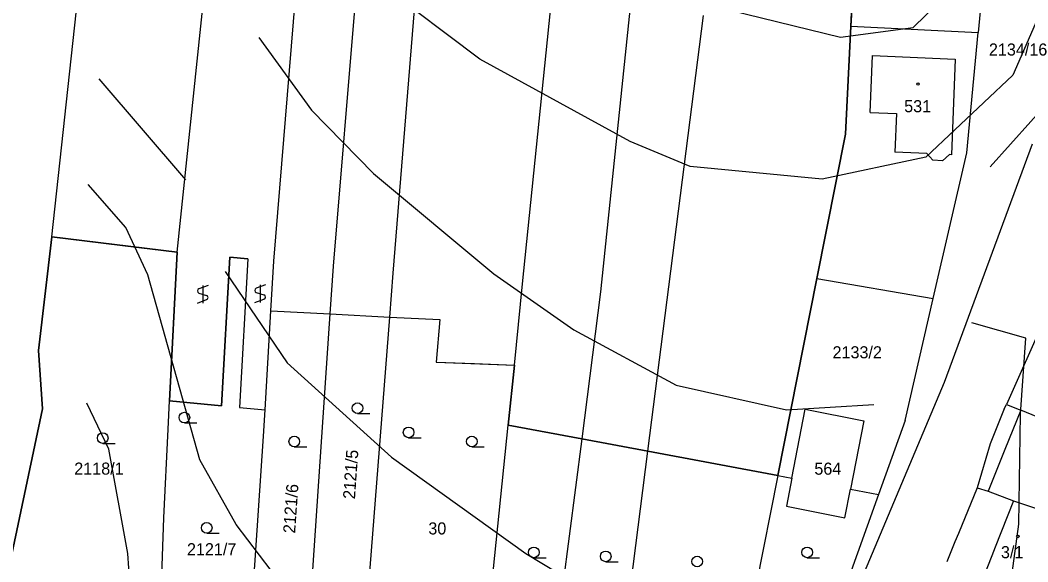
# Model space of a CAD drawing. Extents: x -555860 to -552701, y -1187050 to -1182291.
# Drawn here: x -554286.6 to -554144.7, y -1184272.3 to -1184196.1 of the extents above; entities that cross this region are included whole.
import ezdxf

# ---------------------------------------------------------------- set-up
doc = ezdxf.new("R2010")
doc.units = 0
for name, color, linetype in [('CYKLISTI_stav', 7, 'Continuous'), ('LEG_2b', 7, 'Continuous'), ('Level 25', 7, 'Continuous'), ('Level 32', 7, 'Continuous'), ('Level 40', 7, 'Continuous'), ('Level 41', 7, 'Continuous'), ('navrh_BV', 7, 'Continuous')]:
    doc.layers.add(name, color=color, linetype=linetype)

msp = doc.modelspace()

# ---------------------------------------------------------------- linework, layer by layer
at = {"layer": 'CYKLISTI_stav'}
for p, q in [((-554166.91, -1184209.06), (-554166.56, -1184201.06)), ((-554145.7, -1184250.96), (-554147.93, -1184256.49)), ((-554147.93, -1184256.49), (-554148.78, -1184258.61)), ((-554148.78, -1184258.61), (-554150.28, -1184262.35)), ((-554146.72, -1184263.71), (-554149.28, -1184270.25)), ((-554149.28, -1184270.25), (-554149.75, -1184271.45)), ((-554149.75, -1184271.45), (-554150.87, -1184274.32))]:
    msp.add_line(p, q, dxfattribs=at)
for points in [[(-554166.56, -1184201.06), (-554154.9, -1184201.54), (-554155.44, -1184215.01), (-554155.74, -1184215), (-554156.69, -1184215.85), (-554158.09, -1184215.8), (-554158.91, -1184214.86), (-554163.44, -1184214.66)], [(-554166.91, -1184209.06), (-554163.19, -1184209.23), (-554163.44, -1184214.66)], [(-554177.93, -1184260.54), (-554178.69, -1184264.49), (-554170.44, -1184266.12), (-554169.65, -1184262.09)]]:
    msp.add_lwpolyline(points, dxfattribs=at)
at = {"layer": 'Level 25'}
for p, q in [((-554260.12, -1184233.4), (-554261.42, -1184233.88)), ((-554260.87, -1184233.4), (-554260.87, -1184235.9)), ((-554252.04, -1184233.33), (-554253.34, -1184233.8)), ((-554252.79, -1184233.33), (-554252.79, -1184235.83)), ((-554261.62, -1184235.9), (-554260.32, -1184235.41)), ((-554261.42, -1184234.48), (-554260.32, -1184234.81)), ((-554253.54, -1184235.83), (-554252.24, -1184235.34)), ((-554253.34, -1184234.41), (-554252.24, -1184234.74)), ((-554239.08, -1184251.44), (-554237.33, -1184251.44)), ((-554263.45, -1184252.76), (-554261.7, -1184252.76)), ((-554231.87, -1184254.84), (-554230.12, -1184254.84)), ((-554274.95, -1184255.64), (-554273.2, -1184255.64)), ((-554247.97, -1184256.12), (-554246.22, -1184256.12)), ((-554222.98, -1184256.12), (-554221.23, -1184256.12)), ((-554260.3, -1184268.27), (-554258.55, -1184268.27)), ((-554214.24, -1184271.73), (-554212.49, -1184271.73)), ((-554204.12, -1184272.3), (-554202.37, -1184272.3)), ((-554175.76, -1184271.73), (-554174.01, -1184271.73))]:
    msp.add_line(p, q, dxfattribs=at)
for centre, radius in [((-554160.16, -1184205.06), 0.175), ((-554239.08, -1184250.69), 0.75), ((-554263.45, -1184252.01), 0.75), ((-554231.87, -1184254.09), 0.75), ((-554274.95, -1184254.89), 0.75), ((-554247.97, -1184255.37), 0.75), ((-554222.98, -1184255.37), 0.75), ((-554260.3, -1184267.52), 0.75), ((-554146.09, -1184268.74), 0.175), ((-554214.24, -1184270.98), 0.75), ((-554204.12, -1184271.55), 0.75), ((-554175.76, -1184270.98), 0.75), ((-554191.24, -1184272.26), 0.75)]:
    msp.add_circle(centre, radius, dxfattribs=at)
for centre, start, end in [((-554261.29, -1184234.18), 113.579, 246.421), ((-554253.21, -1184234.11), 113.579, 246.421), ((-554260.45, -1184235.11), 293.574, 66.426), ((-554252.37, -1184235.04), 293.574, 66.426)]:
    msp.add_arc(centre, 0.329, start, end, dxfattribs=at)
at = {"layer": 'Level 32'}
for points in [[(-554252.09, -1184250.93), (-554251.27, -1184236.99), (-554242.91, -1184237.42), (-554234.54, -1184237.86), (-554227.5, -1184238.22), (-554228, -1184244.2), (-554222.6, -1184244.41), (-554216.99, -1184244.62), (-554217.86, -1184253.07), (-554207.51, -1184255), (-554198.2, -1184256.75), (-554179.9, -1184260.17), (-554174.39, -1184232.45), (-554170.35, -1184212.11), (-554169.59, -1184196.9), (-554168.02, -1184165.33)], [(-554287.72, -1184271.23), (-554283.44, -1184250.8), (-554284, -1184242.55), (-554282.09, -1184226.58), (-554269.85, -1184228.08), (-554264.48, -1184228.74), (-554265.53, -1184249.64), (-554258.2, -1184250.34), (-554257.07, -1184229.43), (-554254.53, -1184229.67), (-554255.7, -1184250.59), (-554252.09, -1184250.93)]]:
    msp.add_lwpolyline(points, dxfattribs=at)
at = {"layer": 'Level 40'}
for points in [[(-554275.51, -1184204.35), (-554263.27, -1184218.53)], [(-554257.7, -1184231.47), (-554248.96, -1184244.32), (-554234.29, -1184257.59), (-554215.38, -1184271.13), (-554208.6, -1184275.23), (-554195.67, -1184279.93), (-554182.4, -1184280.28), (-554173.07, -1184277)], [(-554142.98, -1184343.24), (-554147.5, -1184337.46), (-554151.45, -1184325.89), (-554152.01, -1184311.49), (-554145.94, -1184267), (-554145.71, -1184251.53), (-554144.95, -1184240.81), (-554152.59, -1184238.69)]]:
    msp.add_lwpolyline(points, dxfattribs=at)
at = {"layer": 'Level 41'}
for points in [[(-554287.2, -1184091.35), (-554285.23, -1184088.67), (-554282.97, -1184086.83), (-554278.31, -1184086.27), (-554273.52, -1184089.38), (-554271.47, -1184091.67), (-554268.43, -1184096.43), (-554253.48, -1184128.89), (-554246.84, -1184147.23), (-554242.89, -1184155.28), (-554237.67, -1184162.05), (-554228.78, -1184171.08), (-554219.89, -1184177.71), (-554210.86, -1184183.07), (-554193.93, -1184191.68), (-554186.59, -1184194.65), (-554171.07, -1184198.46), (-554160.82, -1184197.11), (-554151.81, -1184188.29), (-554148.13, -1184175.7)], [(-554134.61, -1184175.88), (-554146.82, -1184203.79), (-554159.07, -1184215.37), (-554173.67, -1184218.46), (-554192.23, -1184216.66), (-554200.7, -1184213.13), (-554221.87, -1184201.56), (-554235.7, -1184191.12)], [(-554252.97, -1184198.5), (-554245.57, -1184208.76), (-554236.82, -1184217.65), (-554219.89, -1184231.76), (-554208.6, -1184239.66), (-554194.21, -1184247.43), (-554178.69, -1184250.93), (-554166.37, -1184250.16)], [(-554149.99, -1184216.73), (-554138.56, -1184203.94)], [(-554170.72, -1184288.43), (-554177.98, -1184299.04), (-554182.18, -1184304.74), (-554187.41, -1184308.45), (-554191.29, -1184309.4), (-554195.76, -1184309.94), (-554198.16, -1184309.23), (-554201.61, -1184307.2), (-554205.29, -1184304.49), (-554220.31, -1184292.58), (-554251.22, -1184273.53), (-554256.16, -1184267.04), (-554261.25, -1184257.95), (-554268.58, -1184231.9), (-554271.68, -1184225.27), (-554276.98, -1184219.21)], [(-554143.41, -1184395.46), (-554151.31, -1184389.25), (-554156.95, -1184382.33), (-554166.34, -1184339.47), (-554171.93, -1184328.4), (-554175.07, -1184325.93), (-554184.93, -1184323.69), (-554192.32, -1184331.98), (-554196.58, -1184331.98), (-554200.16, -1184331.76), (-554205.77, -1184328.84), (-554227.79, -1184312.2), (-554252.07, -1184297.52), (-554266.04, -1184287.64), (-554269.56, -1184283.13), (-554270.97, -1184277.34), (-554271.4, -1184271.13), (-554274.08, -1184256.46), (-554277.17, -1184249.99)]]:
    msp.add_lwpolyline(points, dxfattribs=at)
at = {"layer": 'navrh_BV'}
for p, q in [((-554168.02, -1184165.33), (-554169.59, -1184196.9)), ((-554282.09, -1184226.58), (-554277.56, -1184184.77)), ((-554264.48, -1184228.74), (-554260.07, -1184186.95)), ((-554250.87, -1184230.01), (-554247.43, -1184188.6)), ((-554242.46, -1184230.71), (-554239.05, -1184189.5)), ((-554234.06, -1184231.66), (-554230.7, -1184190.51)), ((-554150.99, -1184190.28), (-554151.69, -1184197.82)), ((-554215.82, -1184233.2), (-554211.68, -1184192.74)), ((-554200.68, -1184194.19), (-554204.84, -1184234.32)), ((-554198.2, -1184256.75), (-554190.38, -1184195.41)), ((-554169.59, -1184196.9), (-554170.35, -1184212.11)), ((-554169.59, -1184196.9), (-554151.69, -1184197.82)), ((-554153.29, -1184214.74), (-554151.69, -1184197.82)), ((-554170.35, -1184212.11), (-554174.39, -1184232.45)), ((-554156.44, -1184247.01), (-554144.04, -1184213.5)), ((-554158, -1184235.25), (-554153.29, -1184214.74)), ((-554282.09, -1184226.58), (-554284, -1184242.55)), ((-554264.48, -1184228.74), (-554282.09, -1184226.58)), ((-554265.53, -1184249.64), (-554264.48, -1184228.74)), ((-554257.07, -1184229.43), (-554258.2, -1184250.34)), ((-554254.53, -1184229.67), (-554257.07, -1184229.43)), ((-554254.53, -1184229.67), (-554255.7, -1184250.59)), ((-554251.27, -1184236.99), (-554250.87, -1184230.01)), ((-554242.91, -1184237.42), (-554242.46, -1184230.71)), ((-554234.54, -1184237.86), (-554234.06, -1184231.66)), ((-554174.39, -1184232.45), (-554179.9, -1184260.17)), ((-554174.39, -1184232.45), (-554158, -1184235.25)), ((-554216.99, -1184244.62), (-554215.82, -1184233.2)), ((-554204.84, -1184234.32), (-554207.51, -1184255)), ((-554161.94, -1184252.42), (-554158, -1184235.25)), ((-554252.09, -1184250.93), (-554251.27, -1184236.99)), ((-554251.27, -1184236.99), (-554242.91, -1184237.42)), ((-554245.62, -1184277.42), (-554242.91, -1184237.42)), ((-554242.91, -1184237.42), (-554234.54, -1184237.86)), ((-554237.71, -1184278.66), (-554234.54, -1184237.86)), ((-554234.54, -1184237.86), (-554227.5, -1184238.22)), ((-554227.5, -1184238.22), (-554228, -1184244.2)), ((-554142.19, -1184237.83), (-554147.7, -1184250.19)), ((-554284, -1184242.55), (-554283.44, -1184250.8)), ((-554228, -1184244.2), (-554216.99, -1184244.62)), ((-554217.86, -1184253.07), (-554216.99, -1184244.62)), ((-554170.72, -1184280.97), (-554156.44, -1184247.01)), ((-554265.72, -1184253.62), (-554265.53, -1184249.64)), ((-554258.2, -1184250.34), (-554265.53, -1184249.64)), ((-554283.44, -1184250.8), (-554287.72, -1184271.23)), ((-554255.7, -1184250.59), (-554252.09, -1184250.93)), ((-554252.3, -1184254.62), (-554252.09, -1184250.93)), ((-554177.93, -1184260.54), (-554176.05, -1184250.81)), ((-554176.05, -1184250.81), (-554167.77, -1184252.49)), ((-554148.03, -1184250.79), (-554149.98, -1184255.71)), ((-554148.03, -1184250.79), (-554147.7, -1184250.19)), ((-554147.7, -1184250.19), (-554145.7, -1184250.96)), ((-554136.99, -1184254.52), (-554145.7, -1184250.96)), ((-554167.77, -1184252.49), (-554169.65, -1184262.09)), ((-554161.94, -1184252.42), (-554165.72, -1184262.82)), ((-554266.35, -1184266.13), (-554265.72, -1184253.62)), ((-554220.75, -1184281.28), (-554217.86, -1184253.07)), ((-554207.51, -1184255), (-554217.86, -1184253.07)), ((-554254.11, -1184281.69), (-554252.3, -1184254.62)), ((-554207.51, -1184255), (-554211.06, -1184282.53)), ((-554198.2, -1184256.75), (-554207.51, -1184255)), ((-554201.66, -1184283.9), (-554198.2, -1184256.75)), ((-554179.9, -1184260.17), (-554198.2, -1184256.75)), ((-554149.98, -1184255.71), (-554151.84, -1184261.92)), ((-554179.9, -1184260.17), (-554185.16, -1184286.65)), ((-554179.9, -1184260.17), (-554177.93, -1184260.54)), ((-554169.65, -1184262.09), (-554165.72, -1184262.82)), ((-554151.84, -1184261.92), (-554154.47, -1184268.32)), ((-554151.84, -1184261.92), (-554150.28, -1184262.35)), ((-554150.28, -1184262.35), (-554146.72, -1184263.71)), ((-554165.72, -1184262.82), (-554174.91, -1184288.42)), ((-554146.72, -1184263.71), (-554142.92, -1184264.99)), ((-554266.86, -1184281.14), (-554266.35, -1184266.13)), ((-554154.96, -1184269.52), (-554156.11, -1184272.33)), ((-554154.47, -1184268.32), (-554154.96, -1184269.52))]:
    msp.add_line(p, q, dxfattribs=at)

# ---------------------------------------------------------------- texts
at = {"layer": 'LEG_2b'}
for s, p in [('2134/16', (-554150.17, -1184201.05)), ('531', (-554162.1, -1184209.03)), ('2133/2', (-554172.19, -1184243.67)), ('2118/1', (-554278.95, -1184260.04)), ('564', (-554174.75, -1184260.05)), ('30', (-554229.1, -1184268.46)), ('2121/7', (-554263.08, -1184271.39)), ('3/1', (-554148.48, -1184271.8))]:
    msp.add_text(s, height=1.7, dxfattribs=at).set_placement(p)
for s, p in [('2121/5', (-554239.43, -1184263.53)), ('2121/6', (-554247.86, -1184268.35))]:
    msp.add_text(s, height=1.7, rotation=86, dxfattribs=at).set_placement(p)

doc.saveas('drawing.dxf')
